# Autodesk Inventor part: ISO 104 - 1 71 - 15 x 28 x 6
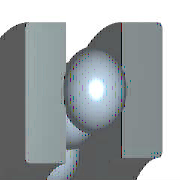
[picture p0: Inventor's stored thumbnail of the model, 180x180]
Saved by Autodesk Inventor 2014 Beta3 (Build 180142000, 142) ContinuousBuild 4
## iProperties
Created: 2012-11
Part Number: ISO 104 - 1 71 - 15 x 28 x 6
Material: Steel, Mild
Description: Rolling bearing-Thrust bearing(Single Direction)
Document SubType Name: Modeling
Standard: ISO 104
Designer: Thomas
Standard Revision: Third edition 2002-02-01
Standards Organization: ISO
Language: en-US
Size Designation: 1 71 - 15 x 28 x 6
Categories: <MemberInstance><Categories><Category DisplayName="Shaft Parts" InternalName="7f7aeb1f-a693-4053-b835-cee3144e0d98" Mnemonic="SHFT"><Category DisplayName="Beari
Density: 1 g/cm^3
Appearance: Steel
IsCustomPart: 0
Author: Thomas
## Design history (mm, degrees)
sketch "Sketch" dims "d3" = 2.64 (= 0.44 x KB)
  geometry: L1 (3, 9.43)-(3, 12.07); L2 (4.32, 10.75)-(1.68, 10.75); L3 (1.8, 11.3)-(1.8, 14); L4 (1.8, 14)-(0, 14); L5 (1.8, 7.5)-(0, 7.5); L6 (4.2, 11.3)-(4.2, 14); L7 (4.2, 14)-(6, 14); L8 (6, 14)-(6, 7.5); L9 (6, 7.5)-(4.2, 7.5); L10 (4.2, 7.5)-(4.2, 10.2); L11 (1.8, 10.2)-(1.8, 7.5); L12 (-0.8, 0)-(4.8, 0) reference; L13 (0, -0.107)-(0, 2.357) reference; 1 further point
  constraints: 22 end point, 5 perpendicular, 3 collinear, 3 parallel, 2 midpoint, 2 point on line, 10 other
  dimensions: "d8" = 15 diameter of L5 L12 (= WD); "d11" = 15 diameter of L9 L12 (= KAD1); "d12" = 21.5 diameter of point (3, 10.75) L12 (= 0.5 x KAD1 + 0.5 x KID1); "d13" = 28 diameter of L4 L12 (= KID1); "d14" = 28 diameter of L7 L12 (= BD); "d15" = 3 distance from line of L13 point (3, 10.75) (= 0.5 x KB); "d16" = 6 distance between parallel lines of L13 L8 (= KB); "d18" = 1.8 distance between parallel lines of L13 L11 (= 0.3 x KB)
revolve "Body" stored, may be unused: angle "d9" = 90 deg
revolve "Ball" stored, may be unused: angle "d10" = 90 deg
pattern_circular "Balls" dims angle "d2" = 360 deg
body "Solid1"
fillet "Fillet1" dims "d4" = 0.3 (= KRS)
fillet "Fillet2" dims "d5" = 0.3 (= KRS)
other parameters: "WD" = 15 [user parameter; used in 2 equation terms], "KAD1" = 15 [user parameter; used in 3 equation terms], "KID1" = 28 [user parameter; used in 3 equation terms], "BD" = 28 [user parameter; used in 2 equation terms], "KB" = 6 [user parameter; used in 6 equation terms], "KRS" = 0.3 [user parameter; used in 2 equation terms], "d0" = 1.2 (= 0.2 x KB), "d6" = 0, "d7" = 0, "d19" = 0, "d46" = 0, "d47" = 0, "WR" = 7.5 (= 0.5 x WD) [user parameter], "BC" = 8900000 [user parameter], "BBA" = 90 deg [user parameter], "BC0" = 1.38e+07 [user parameter], "BR" = 14 (= 0.5 x BD) [user parameter]
